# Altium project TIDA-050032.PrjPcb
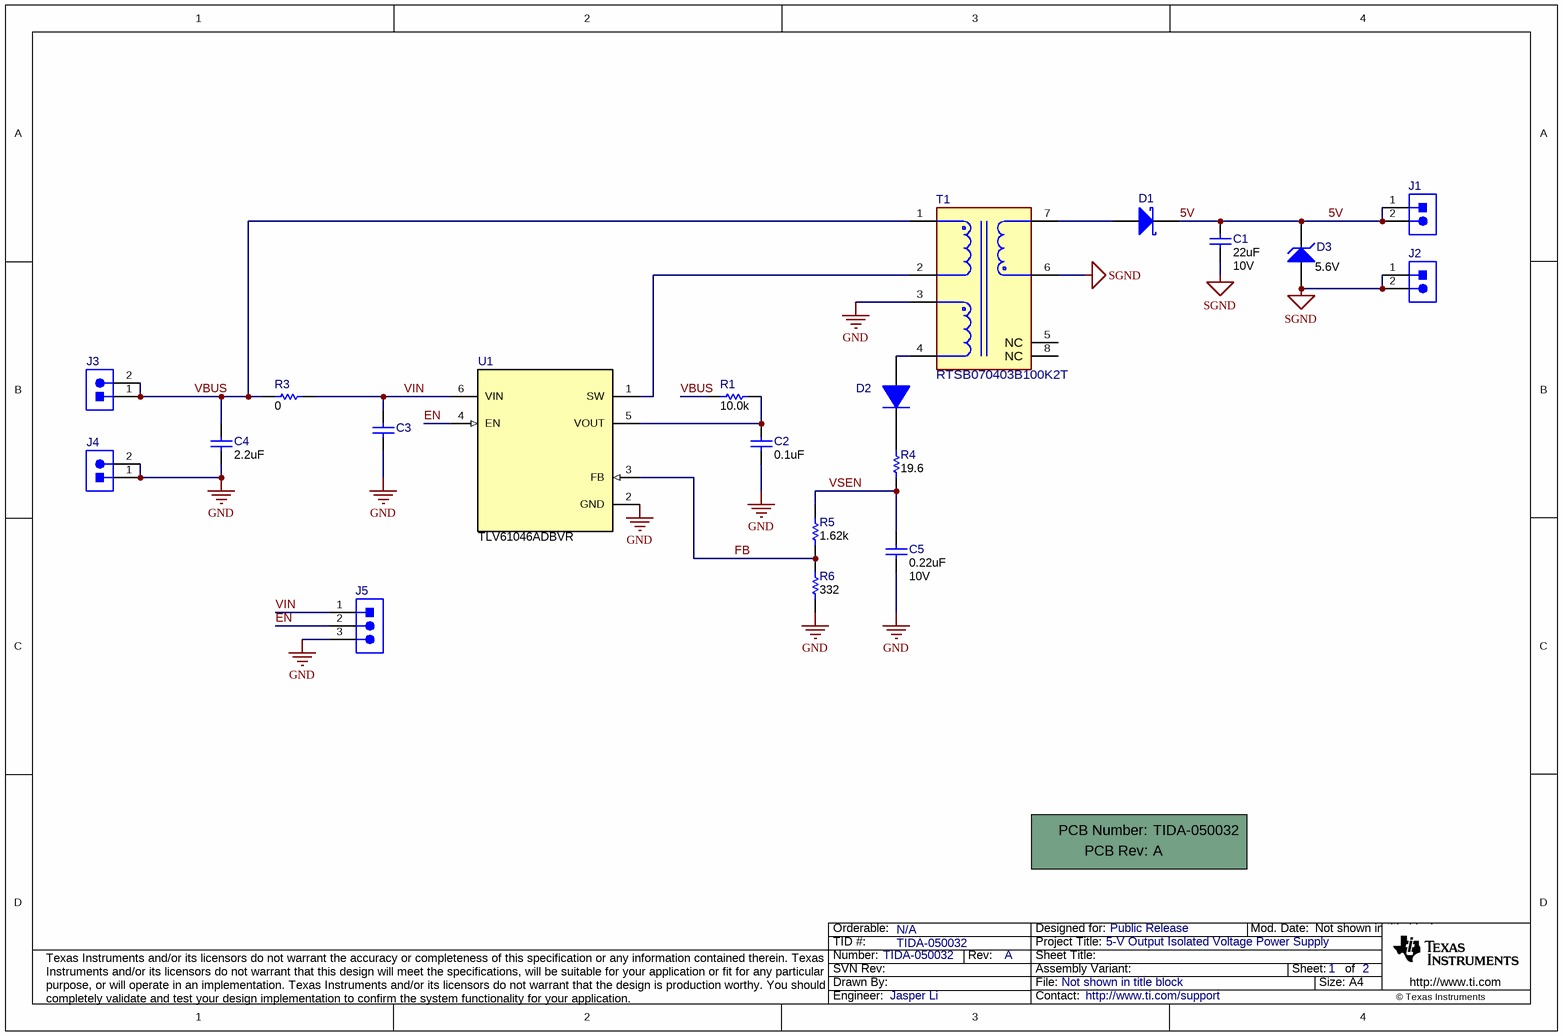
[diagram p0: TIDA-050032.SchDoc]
EVM_Orderable: N/A; PCB_Layout: Jasper; PCB_Rev: A; PRJ_Customer: Public Release; PRJ_Engineer: Jasper Li; PRJ_Number: TIDA-050032; PRJ_Title: 5-V Output Isolated Voltage Power Supply; SCH_Rev: A; TechSupport: http://www.ti.com/support; TID: TIDA-050032
1 sheet, 21 parts. Net scope: global (net labels, ports and power ports of the same name join across sheets).
Board file: TIDA-050032.PcbDoc

## Sheet TIDA-050032.SchDoc
size A4; Date: Not shown in title block; ApprovedBy: Not shown in title block; CheckedBy: Not shown in title block; Author: Not shown in title block; CompanyName: Not shown in title block; Engineer: Not shown in title block; Organization: Not shown in title block; Address1: Not shown in title block; Address2: Not shown in title block; Address3: Not shown in title block; Address4: Not shown in title block; DocumentNumber: 1; Revision: Use project parameter SCH_Rev; SheetNumber: 1; SheetTotal: 2; PageSetup: Record=PageOptions¦CenterHorizontal=True¦CenterVertical=True¦PrintScale=0.91¦XCorrection=1.00¦YCorrection=1.00¦PrintKind=0¦BorderSize=5000000¦LeftOffset=0¦BottomOffset=0¦Orientation=2¦PaperLength=1000¦PaperWidth=1000¦Scale=100¦PaperSource=15¦PrintQuality=600¦MediaType=1¦DitherType=10¦PrintScaleMode=1¦PaperKind=Letter

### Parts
!PCB1  Printed Circuit Board  (value not drawn)  (mechanical)
C1  ValueDisplayed: 22uF  VDC_V: 10V  [0603]  (hidden comment: GRM188R61A226ME15D)
C2  ValueDisplayed: 0.1uF  [0603]  (hidden comment: Capacitor)
C3  Capacitor  [0603]  (value not drawn)
C4  ValueDisplayed: 2.2uF  [0603]  (hidden comment: Capacitor)
C5  ValueDisplayed: 0.22uF  VDC_V: 10V  [0603]  (hidden comment: GRM188R61A224KA01D)
D1  DIODE_SCHOTTKY  [SOD-123]  (value not drawn)
D2  DIODE  [SOD-123]  (value not drawn)
D3  value 5.6V  [SOD-323]  (hidden comment: MMSZ5232BS-7-F)
J1  Header_2x1  [TSW-102-07-G-S]  (value not drawn)
J2  Header_2x1  [TSW-102-07-G-S]  (value not drawn)
J3  Header_2x1  [TSW-102-07-G-S]  (value not drawn)
J4  Header_2x1  [TSW-102-07-G-S]  (value not drawn)
J5  Header_3x1  [TSW-103-07-G-S]  (value not drawn)
R1  ValueDisplayed: 10.0k  [0603]  (hidden comment: Resistor)
R3  ValueDisplayed: 0  [0603]  (hidden comment: RMCF0603ZT0R00)
R4  ValueDisplayed: 19.6  [0603]  (hidden comment: RC0603FR-0719R6L)
R5  ValueDisplayed: 1.62k  [0603]  (hidden comment: RC0603FR-071K62L)
R6  ValueDisplayed: 332  [0603]  (hidden comment: CRCW0603332RFKEA)
T1  RTSB070403B100K2T  [FP-RTSB070403B100K2T_SMD8-MFG]
U1  TLV61046ADBVR  [DBV0006A_N]

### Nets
GND: C2.2 C3.2 C4.2 C5.2 J4.1 J4.2 J5.3 R6.2 T1.3 U1.2(GND)
SGND: C1.2 D3.2(A) J2.1 J2.2 T1.6
5V: C1.1 D1.1(K) D3.1(K) J1.1 J1.2
EN: J5.2 U1.4(EN)
FB: R5.1 R6.1 U1.3(FB)
VBUS: C4.1 J3.1 J3.2 R1.2 R3.1 T1.1
VIN: C3.1 J5.1 R3.2 U1.6(VIN)
VSEN: C5.1 R4.2 R5.2
NetC2_1: C2.1 R1.1 U1.5(VOUT)
NetD1_2: D1.2(A) T1.7
NetD2_1: D2.1(K) R4.1
NetD2_2: D2.2(A) T1.4
NetT1_2: T1.2 U1.1(SW)

Not connected (* = marked no-connect by the designer): T1 5(NC) 8(NC)

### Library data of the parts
!PCB1 = CMP-0003618-2: Manufacturer: Any; PartNumber: TIDA-050032
C1 = CMP-0007324-5: CAP, CERM, 22 uF, 10 V, +/- 20%, X5R, 0603; Manufacturer: MuRata; Polarized: N; Value: 22uF; U/M: EA; Cap_F: 22µF; Value1: Unknown; TaMin_C: -55°C; TaMax_C: 85°C; AEC Category: Q200; SizeArea_mm2: 1.28; SizeAreaWB_mm2: 4.68; SizeX_mm: 1.6; SizeY_mm: 0.8; SizeZ_mm: 1
C2 C3 = CMP-0007334-5: CAP, CERM, 0.1 uF, 16 V, +/- 10%, X5R, 0603; PartNumber: GRM188R61C104KA01D; Manufacturer: MuRata; Polarized: N; Value: 0.1uF; U/M: EA; Cap_F: 100nF; Value1: Unknown; VDC_V: 16V; TaMin_C: -55°C; TaMax_C: 85°C; AEC Category: Q200; SizeArea_mm2: 1.28; SizeAreaWB_mm2: 4.68; SizeX_mm: 1.6; SizeY_mm: 0.8; SizeZ_mm: 1
C4 = CMP-0007356-5: CAP, CERM, 2.2 uF, 35 V, +/- 10%, X5R, 0603; PartNumber: GRM188R6YA225KA12D; Manufacturer: MuRata; Polarized: N; Value: 2.2uF; U/M: EA; Cap_F: 2.2µF; Value1: Unknown; VDC_V: 35V; TaMin_C: -55°C; TaMax_C: 85°C; AEC Category: Q200; SizeArea_mm2: 1.28; SizeAreaWB_mm2: 4.68; SizeX_mm: 1.6; SizeY_mm: 0.8; SizeZ_mm: 1
C5 = CMP-0007322-5: CAP, CERM, 0.22 uF, 10 V, +/- 10%, X5R, 0603; Manufacturer: MuRata; Polarized: N; Value: 0.22uF; U/M: EA; Cap_F: 220nF; Value1: Unknown; TaMin_C: -55°C; TaMax_C: 85°C; AEC Category: Q200; SizeArea_mm2: 1.28; SizeAreaWB_mm2: 4.68; SizeX_mm: 1.6; SizeY_mm: 0.8; SizeZ_mm: 1
D1 = CMP-0028526-2: Diode, Schottky, 40 V, 0.5 A, SOD-123; PartNumber: MBR0540T1G; Manufacturer: ON Semiconductor; Vf_V: 5.1dV; Value: 40V; Value1: 0.5A; Value2: 0.51V; Io_A: 5dA; TJmax_C: 150°C; RJC_CperW: 118; AEC Category: Q101; Green_Lifecycle: Active; Green_REACh: Passed; SizeArea_mm2: 6.545; SizeAreaWB_mm2: 13.095; SizeX_mm: 3.85; SizeY_mm: 1.7; SizeZ_mm: 1.35
D2 = CMP-0076974-2: Diode, Switching, 100 V, 0.15 A, SOD-123; PartNumber: 1N4148W-TP; Manufacturer: Micro Commercial Components; Vf_V: 1.25V; Value: 100V; Value1: 0.15A; Io_A: 1.5dA; TJmax_C: 150°C; AEC Category: Q101; Green_Lifecycle: Not Set; Green_REACh: Incomplete; SizeArea_mm2: 6.545; SizeAreaWB_mm2: 13.095; SizeX_mm: 3.85; SizeY_mm: 1.7; SizeZ_mm: 1.35
D3 = CMP-0005855-3: Diode, Zener, 5.6 V, 200 mW, SOD-323; Manufacturer: Diodes Inc.; SizeZ_mm: 1; SizeX_mm: 2.7; Value1: 0.2W; SizeArea_mm2: 3.645; RJA_CperW: 350; AEC Category: Q101; Power_W: 200mW; SizeAreaWB_mm2: 8.695; SizeY_mm: 1.35
J1-J4 = CMP-0075405-2: Header, 100mil, 2x1, Gold, TH; Manufacturer: Samtec; Pitch_mm: 2.54; Gender: Male; Shrouded: N; Row_Count: 1; Current_A: 6.3A; Voltage_V: 550V; Cert_CSA: Y; Green_Lifecycle: Active; Green_REACh: Passed
J5 = CMP-0075407-2: Header, 100mil, 3x1, Gold, TH; Manufacturer: Samtec; Pitch_mm: 2.54; Gender: Male; Shrouded: N; Row_Count: 1; Current_A: 6.3A; Voltage_V: 550V; Cert_CSA: Y; Green_Lifecycle: Active; Green_REACh: Passed
R1 = CMP-0022746-5: RES, 10.0 k, 1%, 0.1 W, 0603; PartNumber: RC0603FR-0710KL; Manufacturer: Yageo; Value: 10.0k; Res_ohm: 10k; Value_Code: 10k0; Power_W: 100mW; Value2: 0.1W; VDC_V: 75V; TempCo: 100 ppm/C; EIA_Code: E96; AEC Category: Q200; AEC Qualified: N; SizeArea_mm2: 1.28; SizeX_mm: 1.6; SizeY_mm: 0.8; SizeZ_mm: 1; SizeAreaWB_mm2: 4.68
R3 = CMP-0023343-3: RES, 0, 1%, 0.1 W, AEC-Q200 Grade 0, 0603; Manufacturer: Stackpole Electronics Inc; Value: 0; Power_W: 100mW; Value2: 0.1W; TempCo: ppm/C; AEC Category: Q200; AEC Qualified: Y; SizeArea_mm2: 1.28; SizeX_mm: 1.6; SizeY_mm: 0.8; SizeZ_mm: 1; U/M: EA
R4 = CMP-0022863-4: RES, 19.6, 1%, 0.1 W, 0603; Manufacturer: Yageo; Value: 19.6; Value_Code: 19R6; Power_W: 100mW; Value2: 0.1W; VDC_V: 75V; TempCo: 100 ppm/C; EIA_Code: E96; AEC Category: Q200; AEC Qualified: N; SizeArea_mm2: 1.28; SizeX_mm: 1.6; SizeY_mm: 0.8; SizeZ_mm: 1; SizeAreaWB_mm2: 4.68
R5 = CMP-0022884-5: RES, 1.62 k, 1%, 0.1 W, 0603; Manufacturer: Yageo; Value: 1.62k; Value_Code: 1k62; Power_W: 100mW; Value2: 0.1W; VDC_V: 75V; TempCo: 100 ppm/C; EIA_Code: E96; AEC Category: Q200; AEC Qualified: N; SizeArea_mm2: 1.28; SizeX_mm: 1.6; SizeY_mm: 0.8; SizeZ_mm: 1; SizeAreaWB_mm2: 4.68
R6 = CMP-0022337-5: RES, 332, 1%, 0.1 W, AEC-Q200 Grade 0, 0603; Manufacturer: Vishay-Dale; Value: 332; Value_Code: 332R; Power_W: 100mW; Value2: 0.1W; VDC_V: 75V; TempCo: 100 ppm/C; EIA_Code: E96; AEC Category: Q200; AEC Qualified: Y; AEC Grade: 0; SizeArea_mm2: 1.28; SizeX_mm: 1.6; SizeY_mm: 0.8; SizeZ_mm: 1
T1 = CMP-0087597-1: TRANSFORMER SMD; Manufacturer: Sunlord; AEC Qualified: No; Ns1toNp: 1:1:1; DCR_ohm: 1.5d; Ind_H: 10µH; SizeZ_mm: 7.9mm
U1 = CMP-0013231-2: 28-V Output Voltage Boost Converter with Power Diode and Isolation Switch, DBV0006A (SOT-6); Manufacturer: Texas Instruments; Alternate PartNumber: TLV61046ADBVT; SizeX_mm: 2.8; SizeY_mm: 2.9; CompType: IC; SizeZ_mm: 1.45; SizeArea_mm2: 8.12; SizeAreaWB_mm2: 14.82; U/M: EA

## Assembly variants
001: not fitted C3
